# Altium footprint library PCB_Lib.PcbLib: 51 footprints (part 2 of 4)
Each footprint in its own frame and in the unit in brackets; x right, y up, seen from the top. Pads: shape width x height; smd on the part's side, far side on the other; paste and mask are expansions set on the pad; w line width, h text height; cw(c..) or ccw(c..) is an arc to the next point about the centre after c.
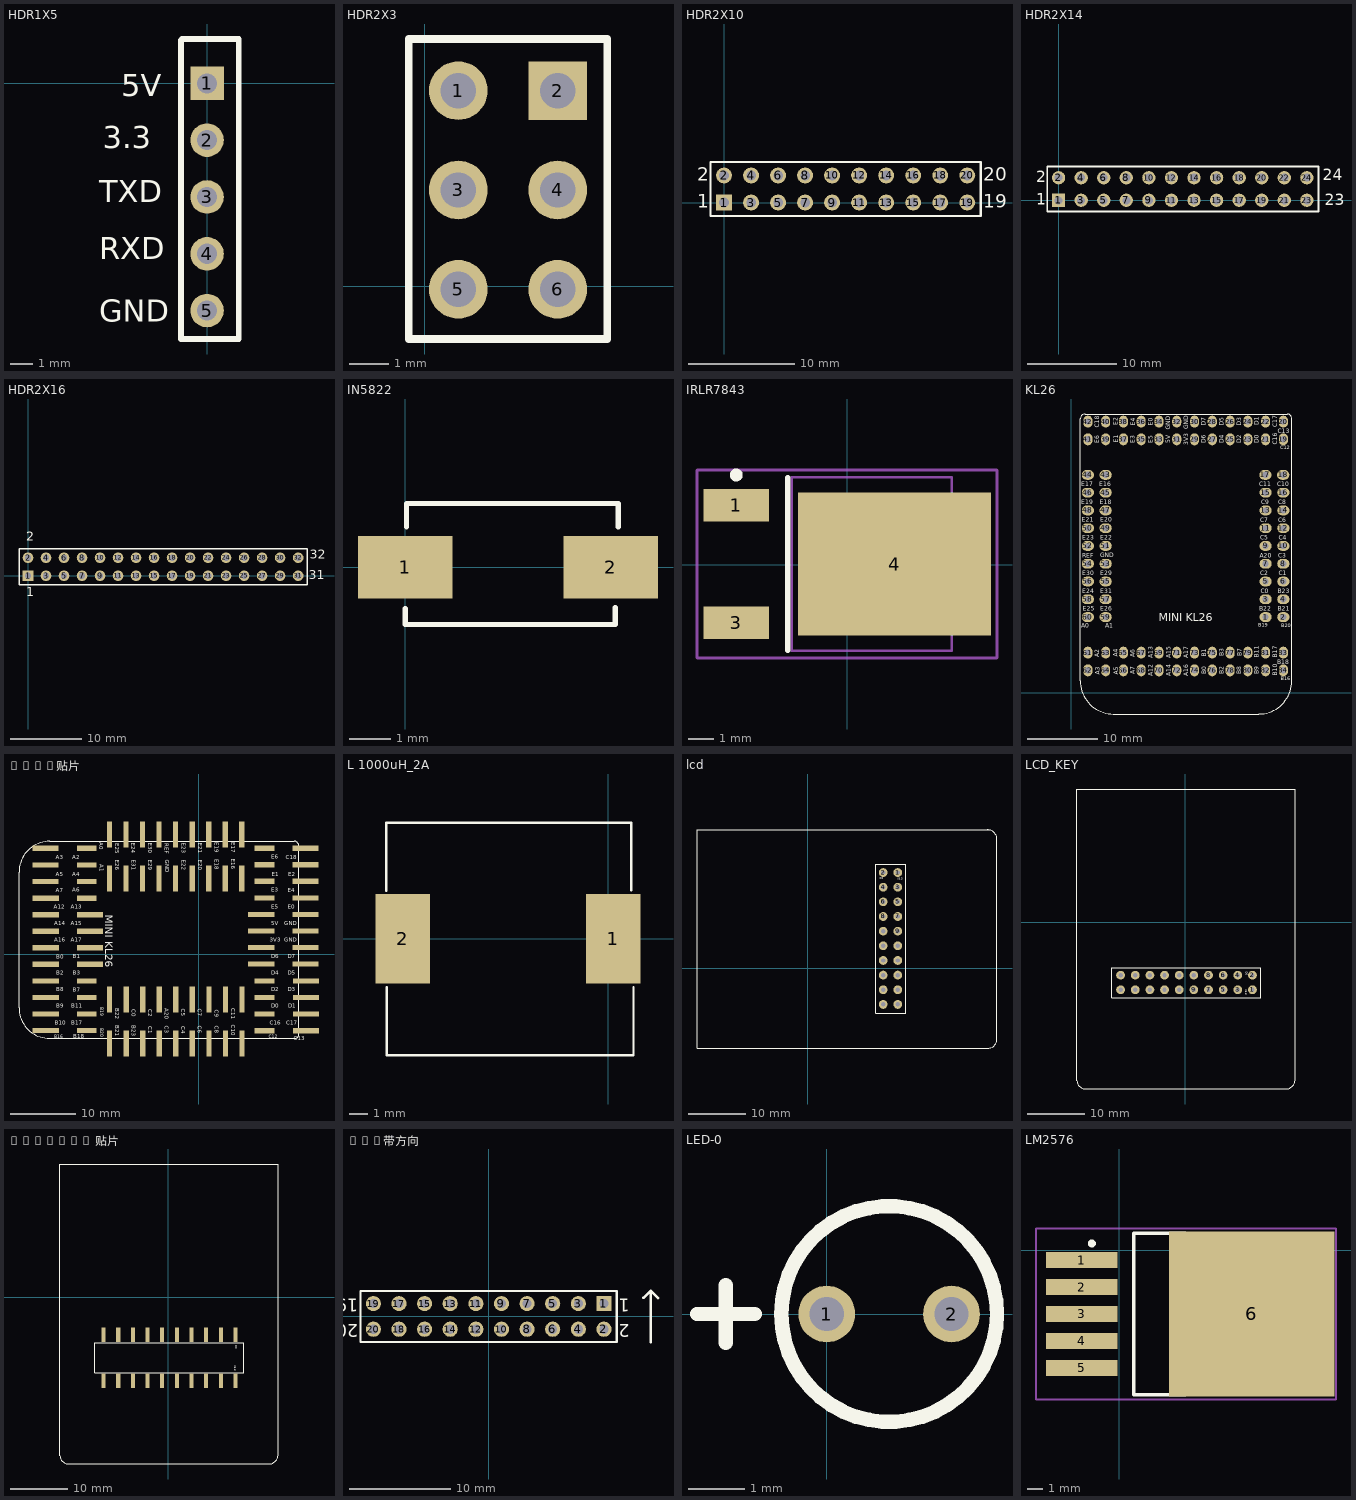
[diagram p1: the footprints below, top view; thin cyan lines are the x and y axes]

## HDR1X5 [mm] "Connector; Header; 4 Position; Right Angle"
pads (5):
  rect 1.5x1.5 hole 0.9: 1(0,0)
  round 1.5 hole 0.9: 2(0,-2.54) 3(0,-5.08) 4(0,-7.62) 5(0,-10.16)
Top Overlay:
  lines w0.254: -1.168,-11.43 1.422,-11.43 1.422,1.702 1.422,1.981 -1.118,1.981 -1.168,1.93 -1.168,-11.43
  text "GND" at -4.826,-10.668 h1
  text "RXD" at -4.826,-7.874 h1
  text "TXD" at -4.826,-5.309 h1
  text "3.3" at -4.659,-2.896 h1
  text "5V" at -3.826,-0.584 h1

## HDR2X3 [mm] "Connector; Header; 3x2 Position"
pads (6):
  round 1.5 hole 0.9: 1(0.864,5.004) 3(0.864,2.464) 4(3.404,2.464) 5(0.864,-0.076) 6(3.404,-0.076)
  rect 1.5x1.5 hole 0.9: 2(3.404,5.004)
Top Overlay:
  lines w0.2: 4.674,1.405 4.674,6.325 -0.406,6.325 -0.406,-1.346 4.674,-1.346 4.674,6.274

## HDR2X10 [mm] "Connector; Header; 10x2 Position"
pads (20):
  rect 1.5x1.5 hole 0.9: 1(0,0)
  round 1.5 hole 0.9: 2(0,2.54) 3(2.54,0) 4(2.54,2.54) 5(5.08,0) 6(5.08,2.54) 7(7.62,0) 8(7.62,2.54) 9(10.16,0) 10(10.16,2.54) 11(12.7,0) 12(12.7,2.54) 13(15.24,0) 14(15.24,2.54) 15(17.78,0) 16(17.78,2.54) 17(20.32,0) 18(20.32,2.54) 19(22.86,0) 20(22.86,2.54)
Top Overlay:
  lines w0.2: -1.27,-1.27 0.635,-1.27 24.13,-1.27 24.13,3.81 0.635,3.81 -1.27,3.81 -1.27,-1.27
  text "20" at 24.384,2.032 h1.27
  text "19" at 24.384,-0.508 h1.27
  text "1" at -2.54,-0.508 h1.27
  text "2" at -2.54,2.032 h1.27

## HDR2X14 [mm]
pads (24):
  rect 1.5x1.5 hole 0.9: 1(0,0)
  round 1.5 hole 0.9: 2(0,2.54) 3(2.54,0) 4(2.54,2.54) 5(5.08,0) 6(5.08,2.54) 7(7.62,0) 8(7.62,2.54) 9(10.16,0) 10(10.16,2.54) 11(12.7,0) 12(12.7,2.54) 13(15.24,0) 14(15.24,2.54) 15(17.78,0) 16(17.78,2.54) 17(20.32,0) 18(20.32,2.54) 19(22.86,0) 20(22.86,2.54) 21(25.4,0) 22(25.4,2.54) 23(27.94,0) 24(27.94,2.54)
Top Overlay:
  lines w0.2: -1.27,-1.27 29.235,-1.27 29.235,3.81 -1.27,3.81 -1.27,-1.27
  text "24" at 29.743,2.261 h1.27
  text "23" at 29.947,-0.559 h1.27
  text "1" at -2.54,-0.508 h1.27
  text "2" at -2.54,2.032 h1.27

## HDR2X16 [mm]
pads (32):
  rect 1.5x1.5 hole 0.9: 1(0,0)
  round 1.5 hole 0.9: 2(0,2.54) 3(2.54,0) 4(2.54,2.54) 5(5.08,0) 6(5.08,2.54) 7(7.62,0) 8(7.62,2.54) 9(10.16,0) 10(10.16,2.54) 11(12.7,0) 12(12.7,2.54) 13(15.24,0) 14(15.24,2.54) 15(17.78,0) 16(17.78,2.54) 17(20.32,0) 18(20.32,2.54) 19(22.86,0) 20(22.86,2.54) 21(25.4,0) 22(25.4,2.54) 23(27.94,0) 24(27.94,2.54) 25(30.48,0) 26(30.48,2.54) 27(33.02,0) 28(33.02,2.54) 29(35.56,0) 30(35.56,2.54) 31(38.1,0) 32(38.1,2.54)
Top Overlay:
  lines w0.2: -1.27,-1.27 -1.27,3.81 39.37,3.81 39.37,-1.27 -1.27,-1.27
  text "32" at 39.776,2.362 h1.27
  text "31" at 39.624,-0.508 h1.27
  text "1" at -0.254,-2.921 h1.27
  text "2" at -0.254,4.953 h1.27

## IN5822 [mm]
pads (2):
  rect 2.27x1.5 smd: 1(0,0) 2(4.92,0)
Top Overlay:
  lines w0.127: 0,-0.991 0,-1.372 5.029,-1.372 5.029,-0.965 ; 0.025,0.965 0.025,1.524 5.105,1.524 5.105,0.965

## IRLR7843 [mm]
height 2.38
pads (3):
  rect 2.55x1.25 smd: 1(-4.3,2.305) 3(-4.3,-2.255)
  rect 7.5x5.55 smd: 4(1.85,0.025)
Top Overlay:
  circle w0.25: c-4.3,3.48 r0.125
  lines w0.2: -2.3,-3.325 -2.3,3.375
Mechanical 13:
  lines w0.1: -2.15,-3.35 4.07,-3.35 4.07,3.4 -2.15,3.4 -2.15,-3.35
Mechanical 15:
  lines w0.1: -0.5,0.025 0.5,0.025 ; 0,-0.475 0,0.525 ; -5.825,-3.625 5.825,-3.625 5.825,3.675 -5.825,3.675 -5.825,-3.625
3D body: height 2.38, standoff 0.46, extent -2.15,-3.35 4.07,3.4

## KL26 [mm]
pads (84):
  oval 1.75x1.397 hole 0.9: 1(27.813,10.795) 2(30.353,10.795) 3(27.813,13.335) 4(30.353,13.335) 5(27.813,15.875) 6(30.353,15.875) 7(27.813,18.415) 8(30.353,18.415) 9(27.813,20.955) 10(30.353,20.955) 11(27.813,23.495) 12(30.353,23.495) 13(27.813,26.035) 14(30.353,26.035) 15(27.813,28.575) 16(30.353,28.575) 17(27.788,31.115) 18(30.328,31.115) 43(4.953,31.115) 44(2.413,31.115) 45(4.953,28.575) 46(2.413,28.575) 47(4.953,26.035) 48(2.413,26.035) 49(4.953,23.495) 50(2.413,23.495) 51(4.953,20.955) 52(2.413,20.955) 53(4.953,18.415) 54(2.413,18.415) 55(4.953,15.875) 56(2.413,15.875) 57(4.953,13.335) 58(2.413,13.335) 59(4.953,10.795) 60(2.413,10.795)
  oval 1.3x1.7 hole 0.9: 19(30.353,36.195) 20(30.353,38.735) 21(27.813,36.195) 22(27.813,38.735) 23(25.273,36.195) 24(25.273,38.735) 25(22.733,36.195) 26(22.733,38.735) 27(20.193,36.195) 28(20.193,38.735) 29(17.653,36.195) 30(17.653,38.735) 31(15.113,36.195) 32(15.113,38.735) 33(12.573,36.195) 34(12.573,38.735) 35(10.033,36.195) 36(10.033,38.735) 37(7.493,36.195) 38(7.493,38.735) 39(4.953,36.195) 40(4.953,38.735) 41(2.413,36.195) 42(2.413,38.735) 61(2.413,5.715) 62(2.413,3.175) 63(4.953,5.715) 64(4.953,3.175) 65(7.493,5.715) 66(7.493,3.175) 67(10.033,5.715) 68(10.033,3.175) 69(12.573,5.715) 70(12.573,3.175) 71(15.113,5.715) 72(15.113,3.175) 73(17.653,5.715) 74(17.653,3.175) 75(20.193,5.715) 76(20.193,3.175) 77(22.733,5.715) 78(22.733,3.175) 79(25.273,5.715) 80(25.273,3.175) 81(27.813,5.715) 82(27.813,3.175) 83(30.353,5.715) 84(30.353,3.175)
Top Overlay:
  lines w0.1: 1.328,1.667 ccw(c6.06,1.667) 6.06,-3.066 26.865,-3.066 ccw(c26.865,1.616) 31.547,1.616 31.547,39.214 ccw(c30.943,39.214) 30.943,39.817 2.006,39.817 ccw(c2.006,39.139) 1.328,39.139 1.328,1.667
  text "C10" at 29.515,29.515 h0.64
  text "C11" at 26.899,29.515 h0.64
  text "B16" at 29.98,1.781 h0.5
  text "B18" at 29.505,4.065 h0.64
  text "B10" at 29.476,2.421 h0.64
  text "B17" at 29.45,4.949 h0.64
  text "B9" at 26.83,2.636 h0.64
  text "B11" at 26.83,4.978 h0.64
  text "B8" at 24.33,2.649 h0.64
  text "B7" at 24.383,5.163 h0.64
  text "B2" at 21.821,2.615 h0.64
  text "B3" at 21.838,5.173 h0.64
  text "B0" at 19.339,2.649 h0.64
  text "B1" at 19.305,5.142 h0.64
  text "A16" at 16.776,2.332 h0.64
  text "A17" at 16.776,4.872 h0.64
  text "A14" at 14.236,2.332 h0.64
  text "A15" at 14.236,4.872 h0.64
  text "A12" at 11.696,2.297 h0.64
  text "A13" at 11.696,4.872 h0.64
  text "A7" at 9.144,2.582 h0.64
  text "A6" at 9.094,5.069 h0.64
  text "A5" at 6.721,2.541 h0.64
  text "A4" at 6.69,5.105 h0.64
  text "A3" at 4.085,2.56 h0.64
  text "A2" at 4.066,5.081 h0.64
  text "A1" at 4.893,9.298 h0.64
  text "A0" at 1.48,9.243 h0.64
  text "E17" at 1.489,29.474 h0.64
  text "E16" at 4.055,29.474 h0.64
  text "E18" at 4.111,26.929 h0.64
  text "E19" at 1.489,26.94 h0.64
  text "E21" at 1.534,24.431 h0.64
  text "E20" at 4.168,24.397 h0.64
  text "E22" at 4.168,21.854 h0.64
  text "E23" at 1.591,21.854 h0.64
  text "REF" at 1.637,19.265 h0.64
  text "GND" at 4.168,19.333 h0.64
  text "E29" at 4.168,16.765 h0.64
  text "E30" at 1.602,16.754 h0.64
  text "E24" at 1.577,14.159 h0.64
  text "E31" at 4.154,14.182 h0.64
  text "E26" at 4.185,11.694 h0.64
  text "E25" at 1.653,11.666 h0.64
  text "MINI KL26" at 12.573,10.16 h1.15
  text "C12" at 29.944,34.789 h0.5
  text "C13" at 29.549,37.096 h0.64
  text "C16" at 29.463,35.394 h0.64
  text "C17" at 29.482,37.896 h0.64
  text "D1" at 26.849,38.185 h0.64
  text "D0" at 26.848,35.625 h0.64
  text "D2" at 24.355,35.607 h0.64
  text "D3" at 24.355,38.147 h0.64
  text "D4" at 21.815,35.607 h0.64
  text "D5" at 21.815,38.147 h0.64
  text "D6" at 19.275,35.607 h0.64
  text "D7" at 19.275,38.147 h0.64
  text "GND" at 16.738,37.611 h0.64
  text "3V3" at 16.776,35.384 h0.64
  text "5V" at 14.204,35.617 h0.64
  text "GND" at 14.206,37.592 h0.64
  text "E5" at 11.655,35.607 h0.64
  text "E0" at 11.655,38.147 h0.64
  text "E4" at 9.174,38.151 h0.64
  text "E3" at 9.115,35.607 h0.64
  text "E1" at 6.719,35.706 h0.64
  text "E2" at 6.701,38.183 h0.64
  text "C18" at 4.062,37.841 h0.64
  text "E6" at 4.035,35.607 h0.64
  text "B20" at 30.025,9.364 h0.5
  text "B19" at 26.746,9.419 h0.5
  text "C8" at 29.655,26.936 h0.64
  text "C9" at 27.159,26.924 h0.64
  text "C7" at 27.049,24.368 h0.64
  text "C6" at 29.612,24.362 h0.64
  text "C4" at 29.698,21.814 h0.64
  text "C5" at 27.041,21.814 h0.64
  text "A20" at 26.952,19.259 h0.64
  text "C3" at 29.621,19.288 h0.64
  text "C1" at 29.714,16.759 h0.64
  text "C2" at 27.067,16.783 h0.64
  text "C0" at 27.111,14.226 h0.64
  text "B23" at 29.526,14.192 h0.64
  text "B21" at 29.561,11.681 h0.64
  text "B22" at 26.925,11.658 h0.64

## kl26贴片 [mm]
pads (84):
  rect 0.8x4 smd: 1(-13.691,-6.909) 2(-13.691,-13.691) 3(-11.154,-6.909) 4(-11.154,-13.691) 5(-8.617,-6.909) 6(-8.617,-13.691) 7(-6.08,-6.909) 8(-6.08,-13.691) 9(-3.543,-6.909) 10(-3.543,-13.691) 11(-1.006,-6.909) 12(-1.006,-13.691) 13(1.53,-6.909) 14(1.53,-13.691) 15(4.067,-6.909) 16(4.067,-13.691) 17(6.604,-6.909) 18(6.604,-13.691) 43(6.579,11.608) 44(6.579,18.39) 45(4.042,11.608) 46(4.042,18.39) 47(1.505,11.608) 48(1.505,18.39) 49(-1.032,11.608) 50(-1.032,18.39) 51(-3.569,11.608) 52(-3.569,18.39) 53(-6.106,11.608) 54(-6.106,18.39) 55(-8.642,11.608) 56(-8.642,18.39) 57(-11.179,11.608) 58(-11.179,18.39) 59(-13.716,11.608) 60(-13.716,18.39)
  rect 3x0.8 smd: 19(10.05,-11.7) 21(10.05,-9.163) 23(10.05,-6.626) 25(10.05,-4.089) 35(10.05,8.649) 37(10.05,11.186) 39(10.05,13.722) 41(10.05,16.259) 61(-17.188,16.25) 63(-17.188,13.713) 65(-17.188,11.176) 67(-17.188,8.611) 77(-17.188,-4.074) 79(-17.188,-6.61) 81(-17.188,-9.147) 83(-17.188,-11.684)
  rect 4x0.8 smd: 20(16.408,-11.7) 22(16.408,-9.163) 24(16.408,-6.626) 26(16.408,-4.089) 27(9.55,-1.499) 28(16.332,-1.499) 29(9.55,1.038) 30(16.332,1.038) 31(9.55,3.575) 32(16.332,3.575) 33(9.55,6.112) 34(16.332,6.112) 36(16.332,8.649) 38(16.332,11.186) 40(16.332,13.722) 42(16.332,16.259) 62(-23.52,16.25) 64(-23.52,13.713) 66(-23.52,11.176) 68(-23.47,8.611) 69(-16.688,6.074) 70(-23.47,6.074) 71(-16.688,3.537) 72(-23.47,3.537) 73(-16.688,1) 74(-23.47,1) 75(-16.688,-1.537) 76(-23.47,-1.537) 78(-23.47,-4.074) 80(-23.47,-6.61) 82(-23.47,-9.147) 84(-23.47,-11.684)
Top Overlay:
  lines w0.1: -27.577,-8.196 ccw(c-22.895,-8.196) -22.895,-12.878 14.703,-12.878 ccw(c14.703,-12.274) 15.306,-12.274 15.306,16.663 ccw(c14.628,16.663) 14.628,17.341 -22.844,17.341 ccw(c-22.844,12.609) -27.577,12.609 -27.577,-8.196
  text "B22" at -12.853,-8.256 h0.64
  text "B21" at -12.83,-10.892 h0.64
  text "B23" at -10.319,-10.857 h0.64
  text "C0" at -10.285,-8.442 h0.64
  text "C2" at -7.728,-8.398 h0.64
  text "C1" at -7.752,-11.045 h0.64
  text "C3" at -5.223,-10.952 h0.64
  text "A20" at -5.252,-8.283 h0.64
  text "C5" at -2.697,-8.372 h0.64
  text "C4" at -2.697,-11.029 h0.64
  text "C6" at -0.149,-10.943 h0.64
  text "C7" at -0.143,-8.38 h0.64
  text "C9" at 2.413,-8.49 h0.64
  text "C8" at 2.425,-10.986 h0.64
  text "C10" at 4.957,-10.82 h0.64
  text "C11" at 4.946,-8.286 h0.64
  text "B19" at -15.092,-8.077 h0.5
  text "B20" at -15.147,-11.356 h0.5
  text "E6" at 11.096,14.634 h0.64
  text "C18" at 13.33,14.607 h0.64
  text "E2" at 13.672,11.968 h0.64
  text "E1" at 11.195,11.95 h0.64
  text "E3" at 11.096,9.554 h0.64
  text "E4" at 13.64,9.495 h0.64
  text "E0" at 13.636,7.014 h0.64
  text "E5" at 11.096,7.014 h0.64
  text "GND" at 13.081,4.463 h0.64
  text "5V" at 11.106,4.465 h0.64
  text "3V3" at 10.873,1.893 h0.64
  text "GND" at 13.1,1.931 h0.64
  text "D7" at 13.636,-0.606 h0.64
  text "D6" at 11.096,-0.606 h0.64
  text "D5" at 13.636,-3.146 h0.64
  text "D4" at 11.096,-3.146 h0.64
  text "D3" at 13.636,-5.686 h0.64
  text "D2" at 11.096,-5.686 h0.64
  text "D0" at 11.114,-8.179 h0.64
  text "D1" at 13.674,-8.18 h0.64
  text "C17" at 13.385,-10.813 h0.64
  text "C16" at 10.883,-10.794 h0.64
  text "C13" at 14.503,-13.208 h0.64
  text "C12" at 10.744,-12.878 h0.5
  text "MINI KL26" at -14.351,6.096 h1.15
  text "E25" at -12.845,17.016 h0.64
  text "E26" at -12.817,14.484 h0.64
  text "E31" at -10.329,14.515 h0.64
  text "E24" at -10.352,17.092 h0.64
  text "E30" at -7.757,17.067 h0.64
  text "E29" at -7.746,14.501 h0.64
  text "GND" at -5.178,14.501 h0.64
  text "REF" at -5.246,17.032 h0.64
  text "E23" at -2.657,17.078 h0.64
  text "E22" at -2.657,14.501 h0.64
  text "E20" at -0.114,14.501 h0.64
  text "E21" at -0.08,17.135 h0.64
  text "E19" at 2.429,17.18 h0.64
  text "E18" at 2.418,14.558 h0.64
  text "E16" at 4.963,14.614 h0.64
  text "E17" at 4.963,17.18 h0.64
  text "A0" at -15.268,17.189 h0.64
  text "A1" at -15.213,13.776 h0.64
  text "A2" at -19.43,14.603 h0.64
  text "A3" at -21.951,14.584 h0.64
  text "A4" at -19.406,11.979 h0.64
  text "A5" at -21.97,11.948 h0.64
  text "A6" at -19.442,9.575 h0.64
  text "A7" at -21.929,9.525 h0.64
  text "A13" at -19.639,6.973 h0.64
  text "A12" at -22.214,6.973 h0.64
  text "A15" at -19.639,4.433 h0.64
  text "A14" at -22.179,4.433 h0.64
  text "A17" at -19.639,1.893 h0.64
  text "A16" at -22.179,1.893 h0.64
  text "B1" at -19.369,-0.636 h0.64
  text "B0" at -21.862,-0.67 h0.64
  text "B3" at -19.338,-3.169 h0.64
  text "B2" at -21.896,-3.152 h0.64
  text "B7" at -19.348,-5.714 h0.64
  text "B8" at -21.862,-5.661 h0.64
  text "B11" at -19.533,-8.161 h0.64
  text "B9" at -21.875,-8.161 h0.64
  text "B17" at -19.562,-10.781 h0.64
  text "B10" at -22.09,-10.807 h0.64
  text "B18" at -19.228,-12.878 h0.64
  text "B16" at -22.2,-12.878 h0.5

## L 1000uH_2A [mm]
pads (2):
  rect 3x4.92 smd: 1(0.279,0) 2(-11.278,0)
Top Overlay:
  lines w0.127: -12.192,2.642 -12.192,6.375 1.27,6.375 ; -12.167,-2.667 -12.167,-6.401 1.397,-6.401 1.397,-2.667 ; 1.27,2.667 1.27,6.325

## lcd [mil]
pads (20):
  round 60 hole 30 square: 1(616,654)
  round 60 hole 30: 2(516,654) 3(616,554) 4(516,554) 5(616,454) 6(516,454) 7(616,354) 8(516,354) 9(616,254) 10(516,254) 11(616,154) 12(516,154) 13(616,54) 14(516,54) 15(616,-46) 16(516,-46) 17(616,-146) 18(516,-146) 19(616,-246) 20(516,-246)
Top Overlay:
  lines w5: 1225,945.22 cw(c1228.78,881.22) 1292.77,885 1292.77,-486 ; 1235,945.22 -754.47,945.22 -754.47,-544.27 1236,-544.27 ccw(c1230.67,-482.26) 1292.69,-477.01 ; 466,-306 668.6,-306 668.6,709 466,709 466,-306
  text "D0" at 494,607 h10
  text "V3.3" at 611,606 h10

## LCD_KEY [mil] "LCD    长5cm，宽3.4cm"
pads (20):
  round 60 hole 30 square: 1(460,-460)
  round 60 hole 30: 2(460,-360) 3(360,-460) 4(360,-360) 5(260,-460) 6(260,-360) 7(160,-460) 8(160,-360) 9(60,-460) 10(60,-360) 11(-40,-460) 12(-40,-360) 13(-140,-460) 14(-140,-360) 15(-240,-460) 16(-240,-360) 17(-340,-460) 18(-340,-360) 19(-440,-460) 20(-440,-360)
Top Overlay:
  lines w5: -680,-1136.77 691,-1136.77 ccw(c687.22,-1072.78) 751.22,-1069 ; -671.01,-1136.69 cw(c-676.26,-1074.67) -738.27,-1080 -738.27,910.47 751.22,910.47 751.22,-1079 ; -500,-512.6 -500,-310 515,-310 515,-512.6 -500,-512.6
  text "V3.3" at 412,-455 h10
  text "D0" at 413,-338 h10

## LCD_KEY 贴片 [mil] "LCD    长5cm，宽3.4cm"
pads (20):
  rect 27.56x98.43 smd: 1(460,-568) 2(460,-255) 3(360,-568) 4(360,-255) 5(260,-568) 6(260,-255) 7(160,-568) 8(160,-255) 9(60,-568) 10(60,-255) 11(-40,-568) 12(-40,-255) 13(-140,-568) 14(-140,-255) 15(-240,-568) 16(-240,-255) 17(-340,-568) 18(-340,-255) 19(-440,-568) 20(-440,-255)
Top Overlay:
  lines w5: -680,-1136.77 691,-1136.77 ccw(c687.22,-1072.78) 751.22,-1069 ; -671.01,-1136.69 cw(c-676.26,-1074.67) -738.27,-1080 -738.27,910.47 751.22,910.47 751.22,-1079 ; -500,-512.6 515,-512.6 515,-310 -500,-310 -500,-512.6
  text "D0" at 457,-326 h10
  text "V3.3" at 453,-463 h10

## LCD带方向 [mm]
pads (20):
  rect 1.5x1.5 hole 0.9: 1(11.43,1.27)
  round 1.5 hole 0.9: 2(11.43,-1.27) 3(8.89,1.27) 4(8.89,-1.27) 5(6.35,1.27) 6(6.35,-1.27) 7(3.81,1.27) 8(3.81,-1.27) 9(1.27,1.27) 10(1.27,-1.27) 11(-1.27,1.27) 12(-1.27,-1.27) 13(-3.81,1.27) 14(-3.81,-1.27) 15(-6.35,1.27) 16(-6.35,-1.27) 17(-8.89,1.27) 18(-8.89,-1.27) 19(-11.43,1.27) 20(-11.43,-1.27)
Top Overlay:
  lines w0.2: -12.7,-2.54 -12.7,2.54 10.795,2.54 12.7,2.54 12.7,-2.54 10.795,-2.54 -12.7,-2.54
  lines w0.254: 15.342,1.854 15.354,1.867 15.38,1.867 16.078,2.565 ; 16.078,-2.565 16.078,2.565 ; 16.789,1.829 16.078,2.54 16.078,2.565
  text "20" at -12.954,-0.762 h1.27
  text "19" at -12.954,1.778 h1.27
  text "1" at 13.97,1.778 h1.27
  text "2" at 13.97,-0.762 h1.27

## LED-0 [mm] "Typical INFRARED GaAs LED; 2 Leads"
pads (2):
  round 1 hole 0.6: 1(0,0) 2(2.2,0)
Top Overlay:
  circle w0.254: c1.1,0 r1.9
  lines w0.254: -2.286,0 -1.27,0 ; -1.778,-0.508 -1.778,0.508

## LM2576 [mm]
height 4.572
pads (6):
  rect 4.5x1 smd: 1(-2.365,-0.609) 2(-2.365,-2.311) 3(-2.365,-4.013) 4(-2.365,-5.715) 5(-2.365,-7.417)
  rect 10.45x10.45 smd: 6(8.37,-4.013)
Top Overlay:
  circle w0.25: c-1.73,0.441 r0.125
  lines w0.2: 4.17,-9.113 0.92,-9.113 0.92,1.087 4.17,1.087
Mechanical 13:
  lines w0.1: 0.92,-9.138 0.92,1.112 10.27,1.112 10.27,-9.138 0.92,-9.138
Mechanical 15:
  lines w0.1: 3.92,-4.013 4.92,-4.013 ; 4.42,-4.513 4.42,-3.513 ; -5.258,-9.413 -5.258,1.387 13.691,1.387 13.691,-9.413 -5.258,-9.413
3D body: height 4.57, standoff 0.46, extent 0.92,-9.138 10.27,1.112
